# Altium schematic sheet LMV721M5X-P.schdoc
size 127 x 101 mm
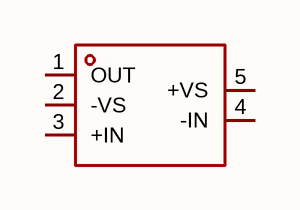
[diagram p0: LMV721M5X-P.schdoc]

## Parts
U?  lmv721m5x-p  [SOT-23-5_L2.9-W1.6-P0.95-LS2.8-BL]  (value not drawn)

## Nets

Not connected (* = marked no-connect by the designer): U? 1(OUT) 2(-VS) 3(+IN) 4(-IN) 5(+VS)

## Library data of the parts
U? = lmv721m5x-p: 放大器数:2;轨到轨:轨到轨输入,轨到轨输出;增益带宽积(GBW):10MHz;输入失调电压(Vos):5mV;压摆率(SR):4.5V/us;输入偏置电流(Ib):100pA;; Manufacturer: TECH PUBLIC(台舟); AddInBom: yes; ModelId: 018c57e721114987ae90467fe9f1d259; ModelTransform: 114.96,110.236,0,0,0,0,0,0,0; Number of Channels: 2; Maximum Power Supply Range (Vdd-Vss): 7V; Gain Bandwidth Product: 10MHz; Vos - Input Offset Voltage: 5mV; Input Offset Voltage Drift(Vos TC): 6uV/℃; Ib - Input Bias Current: 100pA; Input Offset Current(Ios): 1pA; Input Voltage Noise Density: 15nV/√Hz@30kHz; Common Mode Rejection Ratio(CMRR): 80dB; Quiescent Current: 800uA; Output Current: 50mA; Single supply: 2.2V~5.5V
